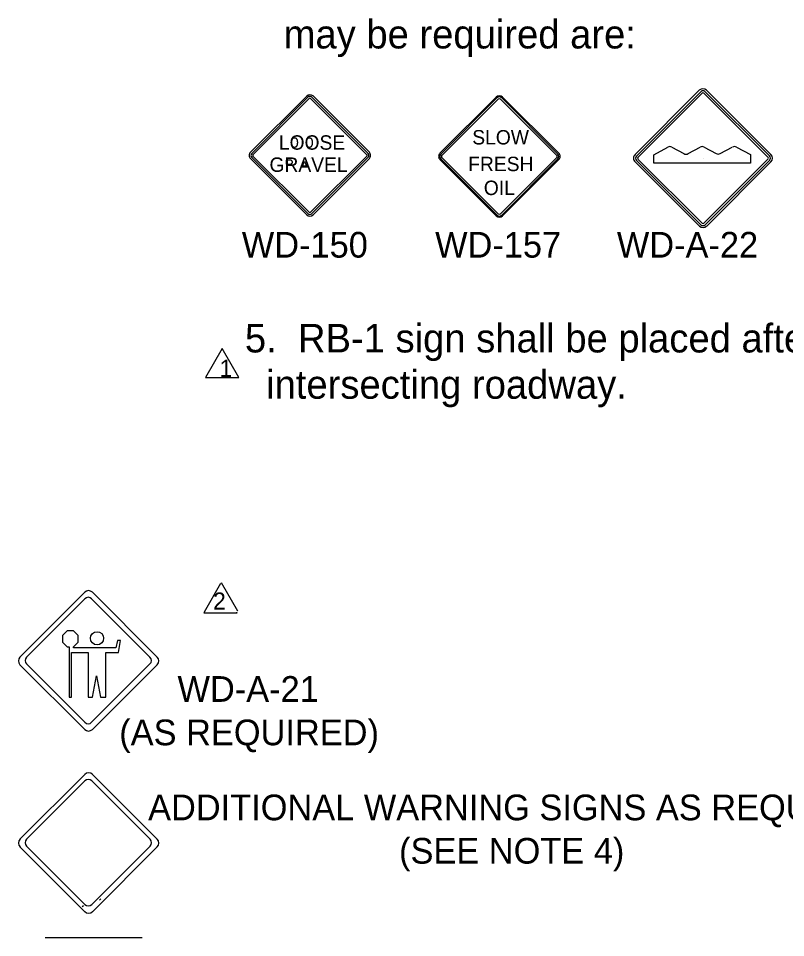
# Model space of a CAD drawing. Extents: x 2195 to 2411, y 202 to 481.
# Drawn here: x 2300.1 to 2365.1, y 284.9 to 362.7 of the extents above; entities that cross this region are included whole.
import ezdxf

# ---------------------------------------------------------------- set-up
doc = ezdxf.new("R2010")
doc.units = 0
for name, color, linetype in [('Level 1', 7, 'Continuous'), ('Level 10', 7, 'Continuous'), ('Level 2', 7, 'Continuous'), ('Level 44', 7, 'Continuous'), ('Level 60', 7, 'Continuous')]:
    doc.layers.add(name, color=color, linetype=linetype)

msp = doc.modelspace()

# ---------------------------------------------------------------- linework, layer by layer
at = {"layer": 'Level 1'}
for p, q in [((2352.361, 351.194), (2357.805, 356.645)), ((2358.421, 356.645), (2363.871, 351.202)), ((2352.482, 351.073), (2357.926, 356.523)), ((2352.604, 350.952), (2358.047, 356.402)), ((2358.178, 356.402), (2363.628, 350.959)), ((2358.299, 356.524), (2363.749, 351.08)), ((2353.943, 351.186), (2355.138, 351.827)), ((2353.943, 350.465), (2353.943, 351.186)), ((2355.488, 351.827), (2356.5, 351.273)), ((2356.85, 351.273), (2357.87, 351.827)), ((2358.219, 351.827), (2359.232, 351.281)), ((2359.582, 351.281), (2360.601, 351.827)), ((2360.951, 351.827), (2362.139, 351.193)), ((2362.139, 351.193), (2362.139, 350.465)), ((2357.812, 345.135), (2352.362, 350.578)), ((2357.933, 345.256), (2352.483, 350.7)), ((2358.054, 345.378), (2352.604, 350.821)), ((2358.044, 350.465), (2353.943, 350.465)), ((2362.139, 350.465), (2358.044, 350.465)), ((2358.154, 350.851), (2358.154, 350.851)), ((2363.628, 350.828), (2358.185, 345.378)), ((2363.75, 350.707), (2358.306, 345.257)), ((2363.871, 350.586), (2358.428, 345.135)), ((2304.235, 310.842), (2303.841, 310.448)), ((2304.792, 310.842), (2304.235, 310.842)), ((2305.186, 310.448), (2304.792, 310.842)), ((2303.841, 310.448), (2303.841, 309.891)), ((2303.841, 309.891), (2304.235, 309.497)), ((2304.792, 309.497), (2305.186, 309.891)), ((2305.186, 309.891), (2305.186, 310.448)), ((2308.506, 310.023), (2308.362, 309.424)), ((2308.756, 310.023), (2308.506, 310.023)), ((2308.593, 309.022), (2308.756, 310.023)), ((2304.235, 309.497), (2304.413, 309.497)), ((2304.413, 309.497), (2304.413, 305.231)), ((2304.792, 309.424), (2304.792, 309.497)), ((2308.362, 309.424), (2304.792, 309.424)), ((2304.609, 305.231), (2304.609, 309.022)), ((2304.609, 309.022), (2306.029, 309.022)), ((2306.029, 309.022), (2306.029, 305.231)), ((2307.517, 305.231), (2307.517, 309.022)), ((2307.517, 309.022), (2308.593, 309.022)), ((2306.405, 305.231), (2306.742, 307.047)), ((2306.742, 307.047), (2307.059, 305.231)), ((2304.413, 305.231), (2304.609, 305.231)), ((2306.029, 305.231), (2306.405, 305.231)), ((2307.059, 305.231), (2307.517, 305.231))]:
    msp.add_line(p, q, dxfattribs=at)
msp.add_lwpolyline([(2317.38, 334.783), (2315.961, 332.313), (2318.799, 332.313)], close=True, dxfattribs=at)
msp.add_circle((2306.778, 310.223), 0.559, dxfattribs=at)
for centre, radius, start, end in [((2358.113, 356.337), 0.436, 45.0349, 135.0349), ((2358.113, 356.337), 0.264, 45.0349, 135.0349), ((2358.113, 356.337), 0.0926, 45.0349, 135.0349), ((2352.669, 350.887), 0.436, 135.03461, 225.03531), ((2355.311, 351.507), 0.364, 61.36492, 118.24621), ((2356.675, 351.593), 0.364, 241.38954, 298.48219), ((2358.045, 351.508), 0.364, 61.6364, 118.48793), ((2359.407, 351.6), 0.364, 241.62621, 298.24621), ((2360.777, 351.508), 0.364, 61.86394, 118.21736), ((2363.563, 350.893), 0.436, 315.03523, 45.03475), ((2352.669, 350.887), 0.264, 135.03461, 225.03531), ((2352.669, 350.887), 0.0926, 135.03461, 225.03531), ((2363.563, 350.893), 0.0926, 315.03523, 45.03475), ((2363.563, 350.893), 0.264, 315.03523, 45.03475), ((2358.119, 345.443), 0.436, 225.03494, 315.03441), ((2358.119, 345.443), 0.264, 225.03494, 315.03441), ((2358.119, 345.443), 0.0926, 225.03494, 315.03441)]:
    msp.add_arc(centre, radius, start, end, dxfattribs=at)
at = {"layer": 'Level 2'}
for p, q in [((2319.776, 351.393), (2324.541, 356.157)), ((2319.883, 351.287), (2324.647, 356.051)), ((2319.989, 351.181), (2324.753, 355.945)), ((2324.868, 355.945), (2329.635, 351.184)), ((2324.974, 356.051), (2329.741, 351.29)), ((2325.08, 356.158), (2329.847, 351.396)), ((2335.827, 351.305), (2340.591, 356.069)), ((2335.897, 351.234), (2340.662, 355.999)), ((2336.003, 351.128), (2340.768, 355.892)), ((2340.953, 355.893), (2345.721, 351.131)), ((2341.059, 355.999), (2345.827, 351.237)), ((2341.13, 356.069), (2345.897, 351.308)), ((2324.544, 346.092), (2319.777, 350.854)), ((2324.65, 346.198), (2319.883, 350.96)), ((2324.756, 346.305), (2319.989, 351.066)), ((2323.172, 350.392), (2323.163, 350.392)), ((2324.841, 350.892), (2324.841, 350.892)), ((2329.635, 351.069), (2324.871, 346.305)), ((2329.741, 350.963), (2324.977, 346.199)), ((2329.847, 350.857), (2325.083, 346.093)), ((2340.594, 346.004), (2335.827, 350.766)), ((2340.665, 346.075), (2335.897, 350.837)), ((2340.771, 346.181), (2336.003, 350.943)), ((2345.721, 350.946), (2340.956, 346.181)), ((2345.827, 350.84), (2341.062, 346.075)), ((2345.897, 350.769), (2341.133, 346.004)), ((2324.544, 346.092), (2324.544, 346.092)), ((2324.666, 346.004), (2324.666, 346.004)), ((2340.594, 346.004), (2340.594, 346.004)), ((2307.084, 288.142), (2306.98, 288.038)), ((2305.626, 287.575), (2305.522, 287.471))]:
    msp.add_line(p, q, dxfattribs=at)
for points in [[(2323.433, 352.586), (2323.424, 352.586), (2323.405, 352.576), (2323.395, 352.567), (2323.386, 352.567), (2323.376, 352.557), (2323.367, 352.548), (2323.358, 352.548), (2323.348, 352.539), (2323.339, 352.529), (2323.329, 352.52), (2323.32, 352.51), (2323.31, 352.501), (2323.31, 352.491), (2323.301, 352.482), (2323.291, 352.463), (2323.291, 352.454), (2323.282, 352.444), (2323.282, 352.435), (2323.273, 352.416), (2323.273, 352.406), (2323.273, 352.397), (2323.263, 352.368), (2323.263, 352.35), (2323.254, 352.331), (2323.254, 352.312), (2323.254, 352.283), (2323.254, 352.265), (2323.254, 352.246), (2323.244, 352.217), (2323.244, 352.198), (2323.254, 352.17), (2323.254, 352.151), (2323.254, 352.132), (2323.254, 352.104), (2323.263, 352.085), (2323.263, 352.066), (2323.263, 352.047), (2323.273, 352.019), (2323.282, 352), (2323.282, 351.981)], [(2323.282, 351.981), (2323.291, 351.972), (2323.291, 351.953), (2323.301, 351.943), (2323.31, 351.934), (2323.32, 351.924), (2323.32, 351.915), (2323.329, 351.905), (2323.339, 351.896), (2323.348, 351.887), (2323.358, 351.877), (2323.367, 351.868), (2323.376, 351.868), (2323.395, 351.858), (2323.405, 351.849), (2323.414, 351.849), (2323.424, 351.839), (2323.433, 351.839), (2323.452, 351.83), (2323.461, 351.83), (2323.471, 351.83), (2323.49, 351.83), (2323.499, 351.83), (2323.509, 351.82), (2323.528, 351.82), (2323.537, 351.83), (2323.547, 351.83), (2323.565, 351.83), (2323.575, 351.83), (2323.584, 351.839), (2323.594, 351.839), (2323.613, 351.839), (2323.622, 351.849), (2323.632, 351.858), (2323.641, 351.858), (2323.65, 351.868), (2323.66, 351.877), (2323.669, 351.887), (2323.679, 351.887), (2323.688, 351.896), (2323.698, 351.905), (2323.707, 351.915), (2323.717, 351.934), (2323.726, 351.943), (2323.726, 351.953), (2323.735, 351.962), (2323.745, 351.972), (2323.745, 351.981), (2323.754, 352.009), (2323.754, 352.028), (2323.764, 352.047), (2323.764, 352.066), (2323.773, 352.094), (2323.773, 352.113), (2323.773, 352.132), (2323.773, 352.161), (2323.783, 352.18), (2323.783, 352.198), (2323.783, 352.227), (2323.783, 352.246), (2323.773, 352.265), (2323.773, 352.293), (2323.773, 352.312), (2323.773, 352.331), (2323.764, 352.359), (2323.764, 352.378), (2323.754, 352.397), (2323.754, 352.416), (2323.754, 352.425), (2323.745, 352.435), (2323.745, 352.444), (2323.735, 352.463), (2323.735, 352.472), (2323.726, 352.482), (2323.717, 352.491), (2323.707, 352.501), (2323.707, 352.51), (2323.698, 352.52), (2323.688, 352.529), (2323.679, 352.539), (2323.669, 352.548), (2323.66, 352.557), (2323.65, 352.557), (2323.641, 352.567), (2323.622, 352.576), (2323.613, 352.576), (2323.603, 352.586), (2323.594, 352.586), (2323.584, 352.595), (2323.565, 352.595), (2323.556, 352.595), (2323.547, 352.595), (2323.528, 352.595), (2323.518, 352.605), (2323.509, 352.605), (2323.49, 352.595), (2323.48, 352.595), (2323.471, 352.595), (2323.452, 352.595), (2323.443, 352.586), (2323.433, 352.586)], [(2324.687, 352.586), (2324.678, 352.586), (2324.659, 352.576), (2324.649, 352.567), (2324.64, 352.567), (2324.63, 352.557), (2324.621, 352.548), (2324.612, 352.548), (2324.602, 352.539), (2324.593, 352.529), (2324.583, 352.52), (2324.574, 352.51), (2324.564, 352.501), (2324.564, 352.491), (2324.555, 352.482), (2324.545, 352.463), (2324.545, 352.454), (2324.536, 352.444), (2324.536, 352.435), (2324.527, 352.416), (2324.527, 352.406), (2324.527, 352.397), (2324.517, 352.368), (2324.517, 352.35), (2324.508, 352.331), (2324.508, 352.312), (2324.508, 352.283), (2324.508, 352.265), (2324.508, 352.246), (2324.498, 352.217), (2324.498, 352.198), (2324.508, 352.17), (2324.508, 352.151), (2324.508, 352.132), (2324.508, 352.104), (2324.517, 352.085), (2324.517, 352.066), (2324.517, 352.047), (2324.527, 352.019), (2324.536, 352), (2324.536, 351.981)], [(2324.536, 351.981), (2324.545, 351.972), (2324.545, 351.953), (2324.555, 351.943), (2324.564, 351.934), (2324.574, 351.924), (2324.574, 351.915), (2324.583, 351.905), (2324.593, 351.896), (2324.602, 351.887), (2324.612, 351.877), (2324.621, 351.868), (2324.63, 351.868), (2324.649, 351.858), (2324.659, 351.849), (2324.668, 351.849), (2324.678, 351.839), (2324.687, 351.839), (2324.706, 351.83), (2324.715, 351.83), (2324.725, 351.83), (2324.744, 351.83), (2324.753, 351.83), (2324.763, 351.82), (2324.782, 351.82), (2324.791, 351.83), (2324.801, 351.83), (2324.819, 351.83), (2324.829, 351.83), (2324.838, 351.839), (2324.848, 351.839), (2324.867, 351.839), (2324.876, 351.849), (2324.886, 351.858), (2324.895, 351.858), (2324.904, 351.868), (2324.914, 351.877), (2324.923, 351.887), (2324.933, 351.887), (2324.942, 351.896), (2324.952, 351.905), (2324.961, 351.915), (2324.971, 351.934), (2324.98, 351.943), (2324.98, 351.953), (2324.989, 351.962), (2324.999, 351.972), (2324.999, 351.981), (2325.008, 352.009), (2325.008, 352.028), (2325.018, 352.047), (2325.018, 352.066), (2325.027, 352.094), (2325.027, 352.113), (2325.027, 352.132), (2325.027, 352.161), (2325.037, 352.18), (2325.037, 352.198), (2325.037, 352.227), (2325.037, 352.246), (2325.027, 352.265), (2325.027, 352.293), (2325.027, 352.312), (2325.027, 352.331), (2325.018, 352.359), (2325.018, 352.378), (2325.008, 352.397), (2325.008, 352.416), (2325.008, 352.425), (2324.999, 352.435), (2324.999, 352.444), (2324.989, 352.463), (2324.989, 352.472), (2324.98, 352.482), (2324.971, 352.491), (2324.961, 352.501), (2324.961, 352.51), (2324.952, 352.52), (2324.942, 352.529), (2324.933, 352.539), (2324.923, 352.548), (2324.914, 352.557), (2324.904, 352.557), (2324.895, 352.567), (2324.876, 352.576), (2324.867, 352.576), (2324.857, 352.586), (2324.848, 352.586), (2324.838, 352.595), (2324.819, 352.595), (2324.81, 352.595), (2324.801, 352.595), (2324.782, 352.595), (2324.772, 352.605), (2324.763, 352.605), (2324.744, 352.595), (2324.734, 352.595), (2324.725, 352.595), (2324.706, 352.595), (2324.697, 352.586), (2324.687, 352.586)], [(2323.172, 350.713), (2322.804, 350.713), (2322.804, 350.392), (2323.172, 350.392)], [(2323.163, 350.392), (2323.182, 350.392), (2323.191, 350.401), (2323.2, 350.401), (2323.21, 350.401), (2323.219, 350.401), (2323.229, 350.411), (2323.238, 350.411), (2323.248, 350.42), (2323.257, 350.42), (2323.257, 350.43), (2323.267, 350.43), (2323.276, 350.439), (2323.285, 350.449), (2323.285, 350.458), (2323.295, 350.458), (2323.304, 350.468), (2323.304, 350.477), (2323.314, 350.486), (2323.314, 350.496), (2323.323, 350.505), (2323.323, 350.515), (2323.323, 350.524), (2323.323, 350.534), (2323.323, 350.543), (2323.323, 350.553), (2323.323, 350.562), (2323.323, 350.572), (2323.323, 350.581), (2323.323, 350.59), (2323.323, 350.609), (2323.314, 350.619), (2323.304, 350.628), (2323.304, 350.638), (2323.295, 350.647), (2323.285, 350.657), (2323.285, 350.666), (2323.276, 350.676), (2323.267, 350.676), (2323.257, 350.685), (2323.257, 350.694), (2323.248, 350.694), (2323.238, 350.704), (2323.229, 350.704), (2323.219, 350.704), (2323.21, 350.713), (2323.2, 350.713), (2323.191, 350.713), (2323.182, 350.713), (2323.172, 350.713)], [(2324.174, 350.212), (2324.353, 350.628), (2324.523, 350.212), (2324.174, 350.212)]]:
    msp.add_lwpolyline(points, dxfattribs=at)
for centre, radius, start, end in [((2324.81, 355.888), 0.381, 45.03492, 135), ((2324.81, 355.888), 0.231, 45.03492, 135), ((2324.81, 355.888), 0.081, 45.03492, 135), ((2340.861, 355.8), 0.381, 45.03492, 135), ((2340.861, 355.8), 0.281, 45.03492, 135), ((2340.861, 355.8), 0.131, 45.03492, 135), ((2320.046, 351.124), 0.381, 135, 225.03489), ((2320.046, 351.124), 0.231, 135, 225.03489), ((2320.046, 351.124), 0.081, 135, 225.03489), ((2329.578, 351.126), 0.081, 315, 45.035), ((2329.578, 351.126), 0.231, 315, 45.035), ((2329.578, 351.126), 0.381, 315, 45.035), ((2336.096, 351.036), 0.381, 135, 225.03489), ((2336.096, 351.036), 0.281, 135, 225.03489), ((2345.628, 351.039), 0.281, 315, 45.035), ((2345.628, 351.039), 0.381, 315, 45.035), ((2336.096, 351.036), 0.131, 135, 225.03489), ((2345.628, 351.039), 0.131, 315, 45.035), ((2324.813, 346.362), 0.381, 225.03483, 315), ((2324.813, 346.362), 0.231, 225.03483, 315), ((2324.813, 346.362), 0.081, 225.03483, 315), ((2340.864, 346.274), 0.381, 225.03483, 315), ((2340.864, 346.274), 0.281, 225.03483, 315), ((2340.864, 346.274), 0.131, 225.03483, 315)]:
    msp.add_arc(centre, radius, start, end, dxfattribs=at)
at = {"layer": 'Level 44'}
for p, q in [((2305.736, 314.125), (2300.242, 308.639)), ((2311.87, 308.639), (2306.386, 314.125)), ((2300.792, 308.635), (2305.736, 313.573)), ((2306.32, 313.573), (2311.258, 308.635)), ((2300.242, 307.989), (2305.736, 302.497)), ((2300.248, 307.989), (2300.242, 307.989)), ((2305.736, 303.109), (2300.792, 308.049)), ((2311.258, 308.049), (2306.32, 303.109)), ((2306.386, 302.497), (2311.87, 307.989)), ((2305.742, 298.694), (2300.248, 293.209)), ((2311.876, 293.209), (2306.391, 298.694)), ((2300.799, 293.204), (2305.742, 298.141)), ((2306.326, 298.141), (2311.264, 293.204)), ((2300.248, 292.558), (2305.742, 287.067)), ((2300.253, 292.558), (2300.248, 292.558)), ((2305.742, 287.677), (2300.799, 292.618)), ((2311.264, 292.618), (2306.326, 287.677)), ((2306.391, 287.067), (2311.876, 292.558)), ((2302.393, 284.87), (2310.588, 284.87))]:
    msp.add_line(p, q, dxfattribs=at)
for centre, radius, start, end in [((2306.06, 313.802), 0.459, 45, 135), ((2306.027, 313.281), 0.413, 45, 135), ((2300.571, 308.313), 0.459, 135, 224.99999), ((2301.088, 308.341), 0.413, 135, 224.99999), ((2310.967, 308.341), 0.413, 315, 45), ((2311.548, 308.313), 0.459, 315, 45), ((2306.027, 303.402), 0.413, 225, 315), ((2306.06, 302.825), 0.459, 225, 315), ((2306.065, 298.371), 0.459, 45, 135), ((2306.033, 297.85), 0.413, 45, 135), ((2300.577, 292.883), 0.459, 135, 224.99999), ((2301.093, 292.911), 0.413, 135, 224.99999), ((2310.972, 292.911), 0.413, 315, 45), ((2311.554, 292.883), 0.459, 315, 45), ((2306.033, 287.971), 0.413, 225, 315), ((2306.065, 287.394), 0.459, 225, 315)]:
    msp.add_arc(centre, radius, start, end, dxfattribs=at)
at = {"layer": 'Level 60'}
for points in [[(2317.234, 314.858), (2315.841, 312.433)], [(2318.716, 312.51), (2317.322, 314.935)], [(2315.841, 312.433), (2315.815, 312.388), (2318.654, 312.388), (2318.628, 312.433)]]:
    msp.add_lwpolyline(points, dxfattribs=at)

# ---------------------------------------------------------------- texts
at = {"layer": 'Level 1'}
msp.add_text('1', height=1.448, rotation=360, dxfattribs=at).set_placement((2317.153, 332.37))
at = {"layer": 'Level 10'}
for s, p in [('may be required are:', (2322.587, 360.184)), ('5.  RB-1 sign shall be placed after every ', (2319.304, 334.434)), ('  intersecting roadway.', (2319.304, 330.515))]:
    msp.add_text(s, height=2.419, dxfattribs=at).set_placement(p)
for s, height, rotation, p in [('WD-150', 2.1774, 360, (2319.042, 342.468)), ('WD-157', 2.177, 360, (2335.421, 342.468)), ('WD-A-22', 2.177, 360, (2350.819, 342.468)), ('WD-A-21', 2.1779, 359.99999, (2313.595, 304.841)), ('(AS REQUIRED)', 2.1779, 359.99999, (2308.657, 301.163)), ('ADDITIONAL WARNING SIGNS AS REQUIRED', 2.17698, 360, (2311.103, 294.809)), ('(SEE NOTE 4)', 2.17698, 360, (2332.367, 291.135))]:
    msp.add_text(s, height=height, rotation=rotation, dxfattribs=at).set_placement(p)
at = {"layer": 'Level 2'}
for s, p in [('LOOSE', (2322.181, 351.609)), ('SLOW', (2338.567, 352.052)), ('GRAVEL', (2321.387, 349.731)), ('FRESH', (2338.221, 349.791)), ('OIL', (2339.545, 347.768))]:
    msp.add_text(s, height=1.22, dxfattribs=at).set_placement(p)
at = {"layer": 'Level 60'}
msp.add_text('2', height=1.448, rotation=360, dxfattribs=at).set_placement((2316.607, 312.657))

doc.saveas('drawing.dxf')
